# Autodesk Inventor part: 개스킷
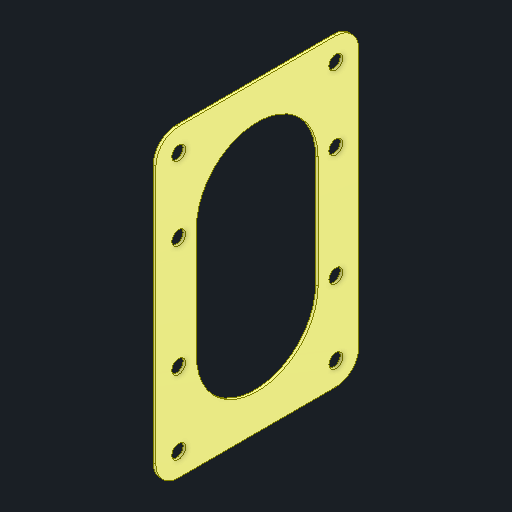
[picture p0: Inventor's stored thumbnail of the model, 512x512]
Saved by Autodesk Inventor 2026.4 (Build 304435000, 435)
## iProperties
Created: 2026-09
Part Number: 개스킷
Material: 스테인리스스틸
Document SubType Name: Modeling
Designer: user
Density: 8 g/cm^3
Appearance: 기본값
Author: jhkim
Sending System: Autodesk Inventor 2027
Preprocessor: ST-DEVELOPER v20.1
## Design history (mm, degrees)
feature "솔리드1"
node "솔리드2"
